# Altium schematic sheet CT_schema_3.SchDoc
size 461 x 327 mm
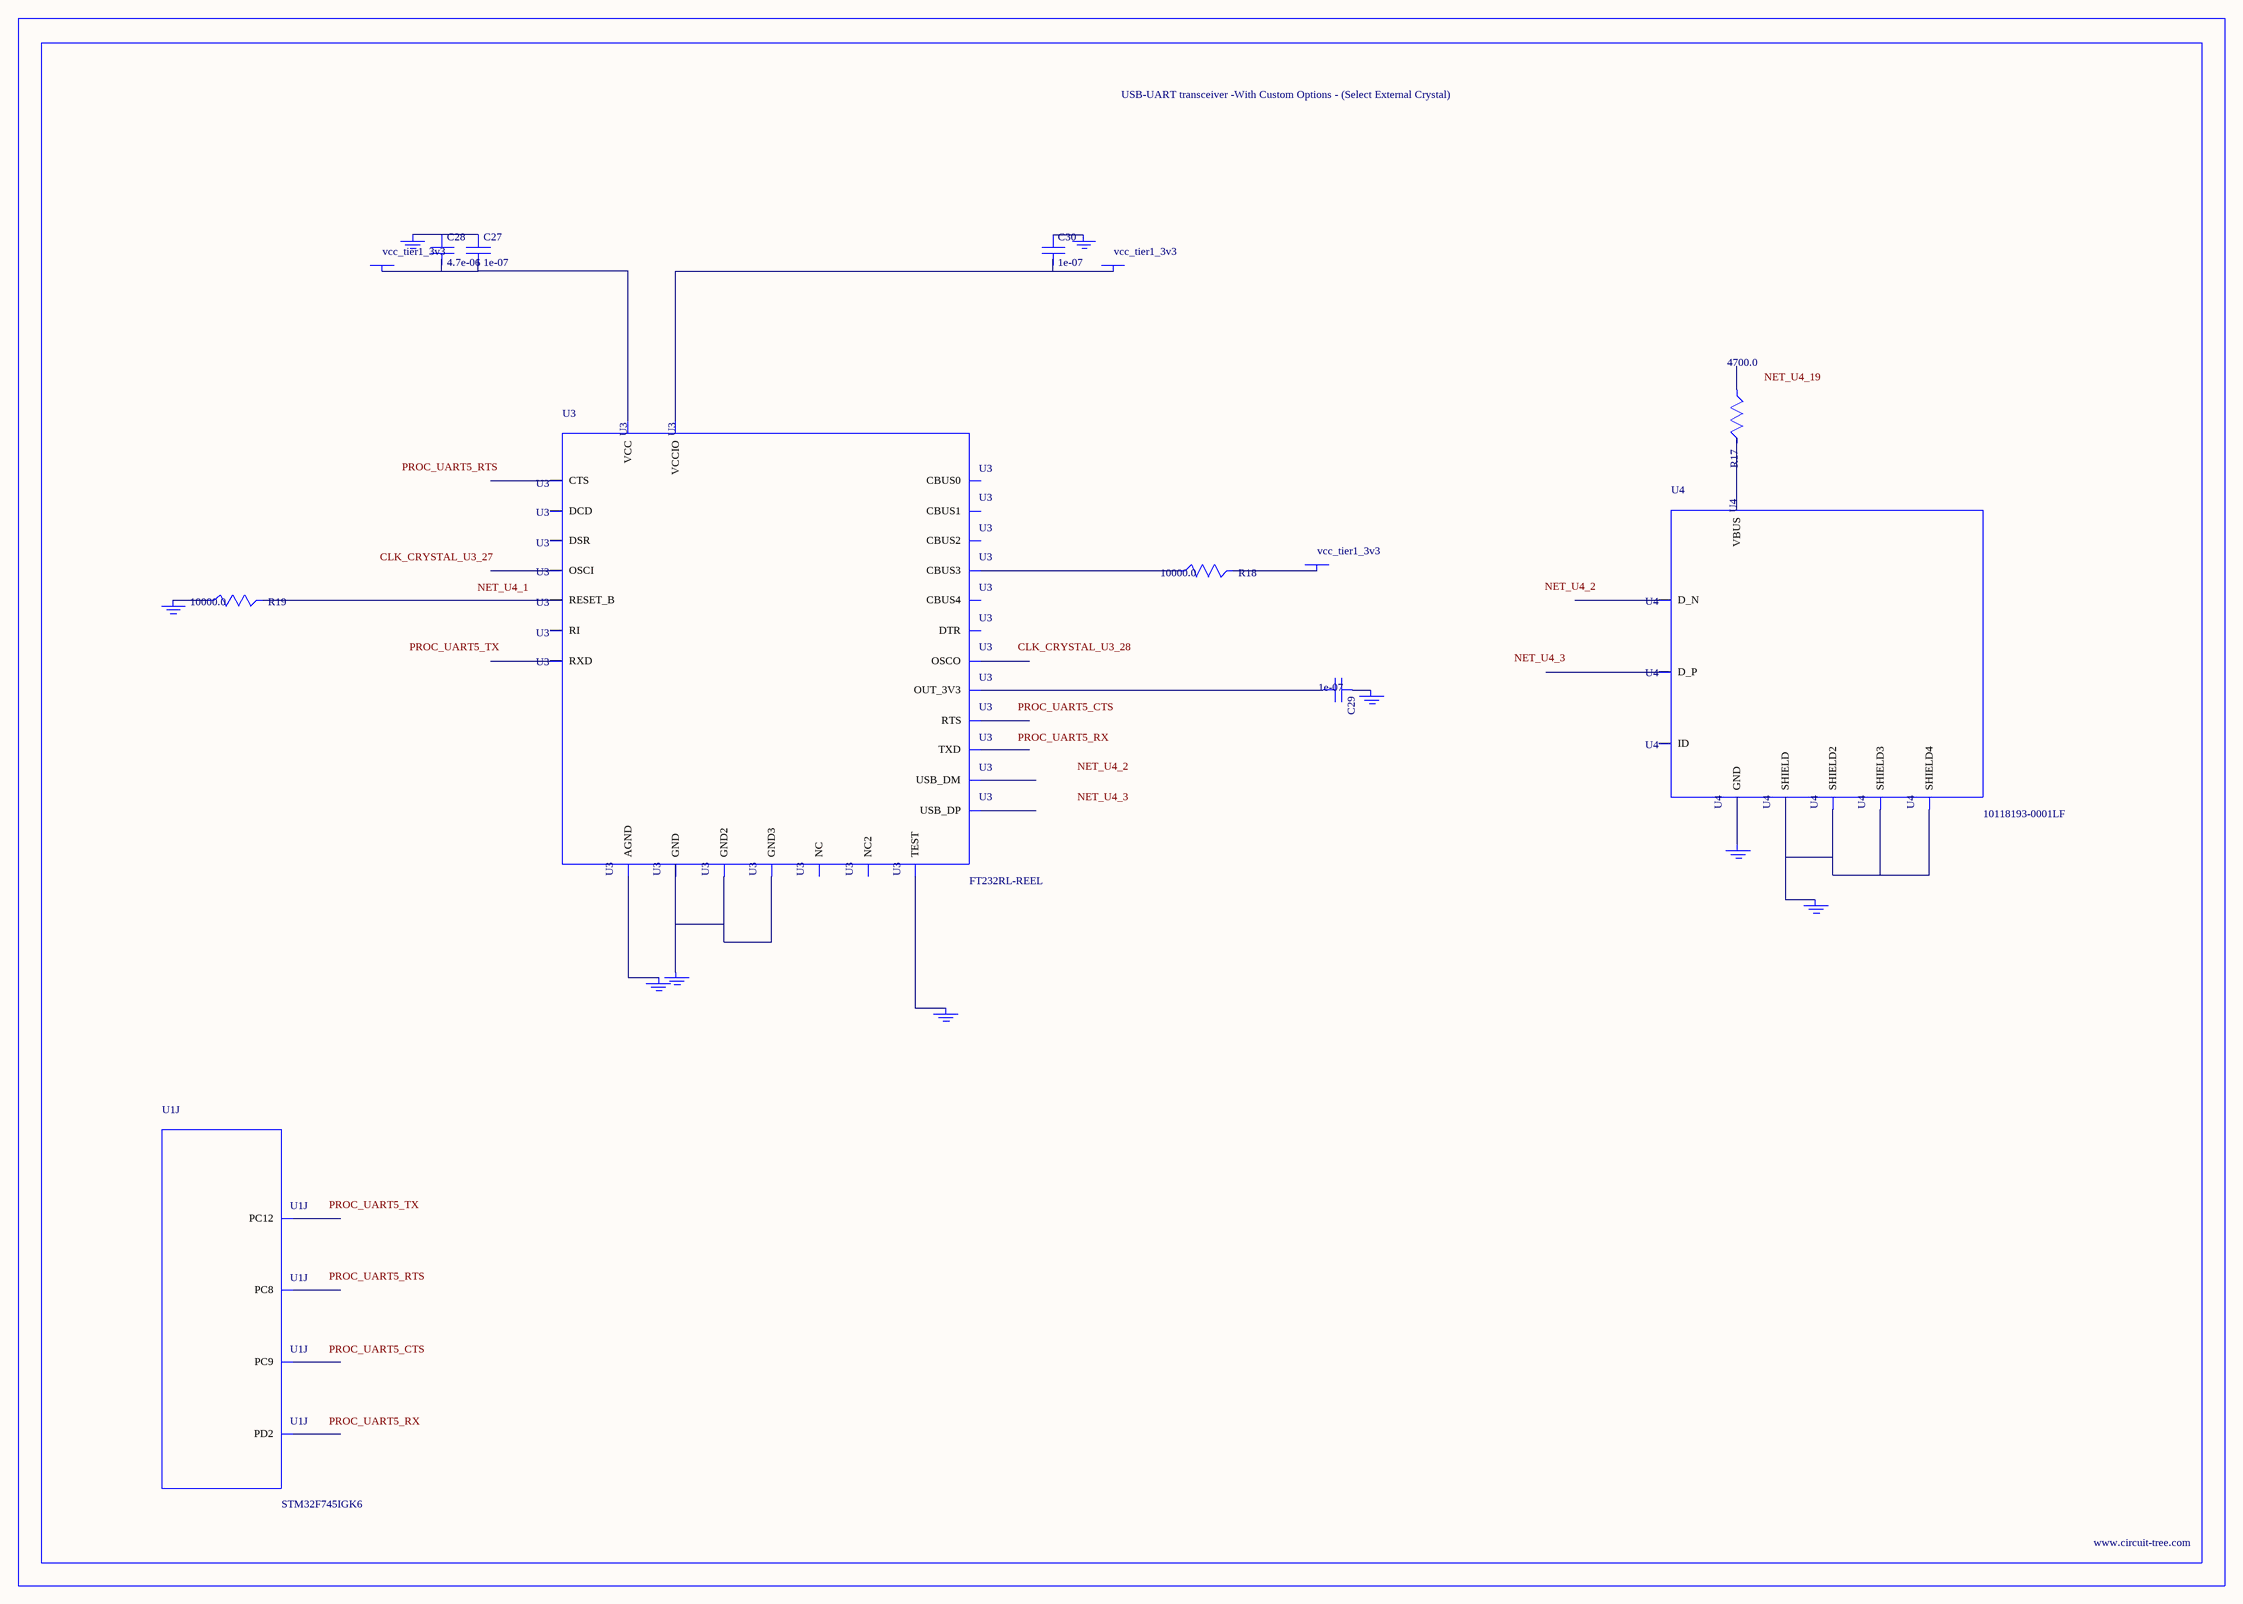
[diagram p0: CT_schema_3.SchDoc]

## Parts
BORDER2  (no value)
C27  1e-07  [C0402]
C28  4.7e-06  [C0805]
C29  1e-07  [C0402]
C30  1e-07  [C0402]
GND_INSTANCE_2_0  (no value)
GND_INSTANCE_2_1  (no value)
GND_INSTANCE_2_2  (no value)
GND_INSTANCE_2_3  (no value)
GND_INSTANCE_2_4  (no value)
GND_INSTANCE_2_5  (no value)
GND_INSTANCE_2_6  (no value)
GND_INSTANCE_2_7  (no value)
GND_INSTANCE_2_8  (no value)
POWER_INSTANCE_2_0  vcc_tier1_3v3
POWER_INSTANCE_2_1  vcc_tier1_3v3
POWER_INSTANCE_2_2  vcc_tier1_3v3
R17  4700.0  [R0603]
R18  10000.0  [R0603]
R19  10000.0  [R0603]
U1  STM32F745IGK6  [UFBGA176_25]  (part J of 16)
U3  FT232RL-REEL  [SSOP-28]
U4  10118193-0001LF  [FCI_10118193-0001LF]

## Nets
NetC27_1: C27.1 C28.1 GND_INSTANCE_2_3.0(GND)
NetC27_2: C27.2 C28.2 POWER_INSTANCE_2_2.0(PWR) U3.20(VCC)
NetC29_1: C29.1 GND_INSTANCE_2_1.0(GND)
NetC29_2: C29.2 U3.17(OUT_3V3)
NetC30_1: C30.1 GND_INSTANCE_2_0.0(GND)
NetC30_2: C30.2 POWER_INSTANCE_2_0.0(PWR) U3.4(VCCIO)
NetGND_INSTANCE_2_2_0: GND_INSTANCE_2_2.0(GND) R19.1
NetGND_INSTANCE_2_4_0: GND_INSTANCE_2_4.0(GND) U3.25(AGND)
NetGND_INSTANCE_2_5_0: GND_INSTANCE_2_5.0(GND) U3.26(TEST)
NetGND_INSTANCE_2_6_0: GND_INSTANCE_2_6.0(GND) U3.7(GND) U3.18(GND2) U3.21(GND3)
NetGND_INSTANCE_2_7_0: GND_INSTANCE_2_7.0(GND) U4.6(SHIELD) U4.7(SHIELD2) U4.8(SHIELD3) U4.9(SHIELD4)
NetGND_INSTANCE_2_8_0: GND_INSTANCE_2_8.0(GND) U4.5(GND)
NetPOWER_INSTANCE_2_1_0: POWER_INSTANCE_2_1.0(PWR) R18.2
NetR17_2: R17.2 U4.1(VBUS)
NetR18_1: R18.1 U3.14(CBUS3)
NetR19_2: R19.2 U3.19(RESET_B)

Not connected (* = marked no-connect by the designer): R17 1; U1 A12(PC12) D12(PD2) F14(PC9) G14(PC8); U3 1(TXD) 2(DTR) 3(RTS) 5(RXD) 6(RI) 8(NC) 9(DSR) 10(DCD) 11(CTS) 12(CBUS4) 13(CBUS2) 15(USB_DP) 16(USB_DM) 22(CBUS1) 23(CBUS0) 24(NC2) 27(OSCI) 28(OSCO); U4 2(D_N) 3(D_P) 4(ID)

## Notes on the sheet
- Labels drawn without touching a wire or pin: CLK_CRYSTAL_U3_27, CLK_CRYSTAL_U3_28, NET_U4_1, NET_U4_2, NET_U4_3, NET_U4_19, PROC_UART5_CTS, PROC_UART5_RTS, PROC_UART5_RX, PROC_UART5_TX

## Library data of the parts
BORDER2 = BORDER_PAGE2
C27 C29 C30 = C0402C104K3RACTU
C28 = C0805C475K4RACTU
GND_INSTANCE_2_0-GND_INSTANCE_2_8 = GND
POWER_INSTANCE_2_0-POWER_INSTANCE_2_2 = PWR
R17 = RC0603JR-074K7L
R18 R19 = RC0603JR-0710KL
